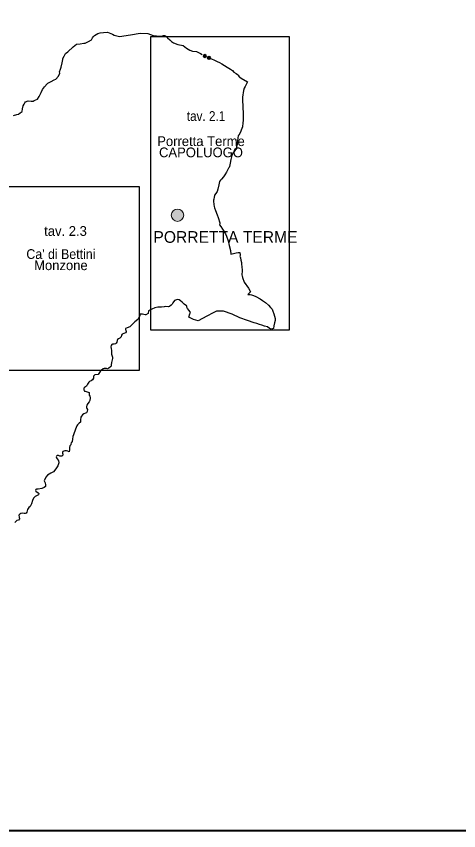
# Model space of a CAD drawing. Extents: x 650468 to 655025, y 889970 to 891591.
# Drawn here: x 653140 to 653594, y 889970 to 890806 of the extents above; entities that cross this region are included whole.
import ezdxf
from ezdxf.enums import TextEntityAlignment as Align

# ---------------------------------------------------------------- set-up
doc = ezdxf.new("R2010")
doc.units = 0
doc.header["$LTSCALE"] = 5.6
doc.header["$PDMODE"] = 32
doc.header["$PDSIZE"] = 2.8
doc.layers.add('61', color=7, linetype='Continuous', lineweight=35)

msp = doc.modelspace()

# ---------------------------------------------------------------- hatches: boundary and pattern name
at = {"layer": '61'}
msp.add_hatch(color=256, dxfattribs=at).paths.add_polyline_path([(653311.55, 890601.85, 1), (653298.83, 890601.85, 1)])

# ---------------------------------------------------------------- linework, layer by layer
at = {"layer": '61', "lineweight": 40}
msp.add_lwpolyline([(653618.27, 891591.08), (653618.27, 889969.62), (652568.28, 889969.62), (652568.28, 891591.08)], close=True, dxfattribs=at)
at = {"layer": '61', "lineweight": 25}
for points in [[(653183.06, 890744.54), (653184.28, 890747.62), (653184.04, 890749.25), (653185.06, 890751.73), (653185.58, 890753.74), (653186.72, 890758.18), (653187.32, 890761.66), (653187.32, 890762.7), (653188.7, 890765.25), (653190.18, 890768.02), (653192.6, 890769.58), (653197.9, 890774.61), (653199.68, 890776.21), (653201.54, 890777.37), (653205.34, 890777.82), (653209.1, 890778.42), (653210.28, 890778.65), (653213.66, 890780.37), (653216.98, 890781.81), (653217.8, 890783.98), (653218.58, 890785.09), (653220.08, 890786.37), (653221.56, 890787.53), (653223.4, 890788.42), (653225.9, 890789.3), (653229.24, 890789.65), (653233.22, 890789.94), (653236.66, 890788.5), (653238.56, 890787.65), (653240.32, 890786.93), (653245.46, 890785.53), (653256.86, 890787.22), (653266.82, 890788.86), (653274.84, 890788.41), (653280.14, 890786.46), (653283.48, 890786.21), (653288.3, 890785.85), (653290.94, 890786.41), (653291.9, 890786.34), (653292.8, 890785.94)], [(653292.8, 890785.94), (653293.7, 890785.33), (653295.02, 890784.09), (653297.26, 890781.98), (653298.98, 890780.29), (653301.26, 890778.81), (653305.46, 890777.1), (653310.86, 890775.98), (653314.46, 890773.57), (653318, 890771.41), (653320.46, 890770.26), (653324.72, 890769.97), (653328.8, 890768.06), (653330.44, 890766.89)], [(653337.54, 890763.38), (653342.48, 890761.58), (653346.08, 890759.69), (653348.18, 890758.66), (653350.58, 890757.22), (653353.4, 890755.61), (653356.1, 890753.74), (653359.64, 890751.9), (653361.56, 890750.46), (653363.1, 890748.77), (653365.58, 890747.26), (653366.96, 890746.5), (653367.5, 890745.66), (653368.66, 890743.98), (653369.18, 890743.46), (653370.76, 890742.45), (653377.22, 890738.7), (653374.64, 890734.02), (653373.8, 890732.17), (653373.1, 890730.06), (653371.82, 890723.1), (653371.88, 890718.1), (653372.2, 890715.66), (653372.36, 890710.54), (653372.52, 890708.66), (653372.74, 890706.25), (653372.72, 890699.14), (653372.3, 890696.73), (653372.14, 890695.49), (653372.08, 890694.09), (653371.88, 890692.33), (653371.72, 890691.81), (653370.14, 890688.3), (653368.06, 890683.62), (653367.64, 890683.54), (653366.9, 890678.26), (653366.6, 890676.69), (653366.4, 890674.41), (653365.96, 890672.17), (653365.64, 890670.18)], [(653136.74, 890704.13), (653140.26, 890705.14), (653142.04, 890705.62), (653143.64, 890707.02), (653145.62, 890708.5), (653145.98, 890711.26), (653146.64, 890714.22), (653147.58, 890716.06), (653148.38, 890717.13), (653149.04, 890718.34), (653151.94, 890719.38), (653154.8, 890719.14), (653156.88, 890719.09), (653158.02, 890719.66), (653161.46, 890720.98), (653162.96, 890723.77), (653165.1, 890727.81), (653166.7, 890730.97), (653168.72, 890733.81), (653171.22, 890736.86), (653172, 890737.42), (653175.44, 890739.06), (653178.6, 890740.74), (653180.26, 890741.49), (653183.06, 890744.54)], [(653365.64, 890670.18), (653365.44, 890669.49), (653364.5, 890668.5), (653363.5, 890667.42), (653362.86, 890666.54), (653362.12, 890665.49), (653361.12, 890663.18), (653360.58, 890661.82), (653359.88, 890658.89), (653359.2, 890655.45), (653358.46, 890651.77), (653358.2, 890650.97), (653357.66, 890650.06), (653355.4, 890646.05), (653353.82, 890643.33), (653352.46, 890641.34), (653350.36, 890638.81), (653349.46, 890637.69), (653348.44, 890636.46), (653347.68, 890633.05), (653346.66, 890628.7), (653346.02, 890626.09), (653344.5, 890624.25), (653343.08, 890622.33), (653343.08, 890621.94), (653343.02, 890620.26), (653342.46, 890618.17), (653342.2, 890617.18), (653342.32, 890616.25), (653342.58, 890612.85), (653342.84, 890610.93), (653343.34, 890609.5), (653344.3, 890606.78), (653345.9, 890602.38), (653347.04, 890599.61), (653348.58, 890594.09), (653348.58, 890593.33), (653348.32, 890592.09), (653349.74, 890590.3), (653351.52, 890587.57)], [(653351.52, 890587.57), (653354.44, 890582.86), (653355.46, 890580.21), (653357.32, 890575.5), (653358.34, 890570.81), (653359.48, 890565.53), (653360.06, 890561.86), (653361.2, 890562.22), (653365.34, 890563.22), (653367.4, 890563.61), (653369.18, 890563.49), (653369.62, 890561.3), (653369.44, 890560.38), (653369.3, 890559.82), (653369.76, 890558.14), (653370.32, 890555.62), (653370.78, 890553.38), (653371.04, 890551.41), (653371.28, 890548.93), (653371.54, 890545.53), (653371.74, 890544.54), (653371.42, 890540.62), (653371.6, 890539.3), (653372.06, 890538.57), (653372, 890538.01), (653373.58, 890533.06), (653378, 890526.74), (653380.22, 890523.05), (653377.58, 890520.3), (653379, 890520.25), (653380, 890520.34), (653381.36, 890520.02), (653383.4, 890519.33), (653385.66, 890518.3), (653390, 890515.89), (653392.6, 890514.26), (653395.74, 890512.1), (653398.66, 890509.5), (653400.64, 890507.18), (653402.3, 890505.26)], [(653302, 890514.22), (653300.3, 890511.9), (653299.76, 890510.58), (653298.62, 890509.54), (653296.84, 890507.94), (653295.82, 890507.89), (653292.58, 890507.97), (653291.42, 890507.89), (653288.64, 890507.5), (653285.04, 890507.22), (653281.76, 890506.57), (653278.78, 890505.38), (653275.38, 890503.62), (653274.98, 890500.98), (653272.8, 890499.38), (653271.86, 890499.58), (653269.34, 890500.13), (653266.94, 890500.18), (653266.08, 890497.81), (653264.44, 890494.7), (653261.52, 890492.26), (653258.8, 890489.58), (653256.28, 890487.26), (653253.62, 890486.14), (653251.96, 890485.57), (653251.7, 890484.53), (653252.18, 890483.73), (653252.5, 890482.14), (653251.9, 890481.09), (653250, 890480.3), (653248.22, 890479.5), (653247.74, 890478.58), (653247.34, 890476.81), (653246.1, 890475.7), (653244.58, 890474.81), (653243.72, 890474.14), (653243.18, 890473.25), (653242.88, 890471.38), (653242.2, 890470.3), (653241.46, 890469.65)], [(653402.3, 890505.26), (653403.2, 890503.29), (653404.22, 890500.62), (653405.48, 890495.78), (653405.36, 890493.73), (653404.74, 890491.37), (653404.06, 890488.3), (653403.78, 890485.49), (653401.76, 890484.9), (653399.84, 890485.54), (653397.54, 890487.01), (653394.48, 890487.78), (653391.76, 890488.86), (653389.58, 890489.5), (653386.8, 890490.62), (653384, 890491.37), (653377.22, 890493.54), (653369.32, 890496.57), (653361.44, 890500.02), (653352.32, 890503.26), (653345.24, 890503.38), (653341.72, 890501.41), (653335.46, 890498.13), (653326.36, 890493.42), (653321.48, 890494.77), (653316.92, 890497.02), (653318.02, 890500.42), (653318.7, 890501.89), (653317.28, 890503.98), (653315.64, 890505.97), (653314.82, 890507.42), (653314.82, 890508.74), (653314.48, 890508.89), (653311.9, 890510.46), (653309.94, 890512.57), (653308.3, 890513.89), (653306.94, 890514.94), (653305.58, 890515.14), (653304.12, 890514.89), (653302, 890514.22)], [(653241.46, 890469.65), (653240.06, 890469.26), (653238.54, 890469.22), (653237.86, 890469.02), (653237.12, 890467.94), (653236.74, 890466.7), (653237.02, 890464.9), (653237.48, 890462.93), (653237.54, 890461.34), (653237.54, 890459.26), (653237.68, 890458.02), (653238.02, 890456.98), (653238.32, 890456.01), (653238.32, 890454.73), (653238.16, 890453.3), (653237.58, 890450.46), (653236.94, 890448.3), (653237, 890446.86), (653236.32, 890445.93), (653234.74, 890444.78), (653233.28, 890444.09), (653232.16, 890444.22), (653229.82, 890444.22), (653229, 890443.89), (653226.94, 890442.29), (653225.72, 890441.18), (653223.68, 890438.26), (653220.46, 890437.89), (653218.94, 890436.61), (653218.9, 890434.29), (653217.98, 890432.69), (653216.36, 890431.82), (653214.86, 890430.97), (653213.98, 890430.21), (653212.92, 890428.41), (653211.64, 890426.14), (653210.82, 890425.66), (653209.74, 890424.94), (653209.16, 890424.21), (653208.92, 890423.34)], [(653208.92, 890423.34), (653208.96, 890422.45), (653209.7, 890421.22), (653210.52, 890420.94), (653212.58, 890420.37), (653214.32, 890419.57), (653214.52, 890418.01), (653214.56, 890417.05), (653215.1, 890415.89), (653215.4, 890414.74), (653215.4, 890413.85), (653215.06, 890411.62), (653214.42, 890410.25), (653213.2, 890408.45), (653212.08, 890406.66), (653211.68, 890405.46), (653211.74, 890404.29), (653212.14, 890403.22), (653212.74, 890402.21), (653212.54, 890400.1), (653211.66, 890398.89), (653210.84, 890398.41), (653209.04, 890397.78), (653207.66, 890396.7), (653206.54, 890395.53), (653205.86, 890394.3), (653205.42, 890391.73), (653205.52, 890389.18), (653204.1, 890388.18), (653202.64, 890386.58), (653201.86, 890385.65), (653200.44, 890381.98), (653198.48, 890376.26), (653197.76, 890374.41), (653197.38, 890371.73), (653196.88, 890369.3), (653196.02, 890368.02), (653195.76, 890366.74), (653195.48, 890365.94), (653194.46, 890364.9)], [(653194.46, 890364.9), (653194.2, 890363.38), (653194.3, 890362.06), (653194.3, 890360.7), (653193.8, 890358.74), (653192.68, 890359.3), (653191.04, 890359.7), (653189.32, 890359.74), (653188.34, 890359.61), (653187.56, 890358.98), (653187.08, 890358.18), (653187.02, 890357.38), (653187.28, 890356.29), (653187.28, 890355.3), (653186.54, 890354.45), (653185.18, 890354.26), (653184.44, 890354.5), (653182.94, 890355.01), (653181.72, 890354.97), (653181.02, 890354.5), (653180.64, 890353.54), (653180.84, 890352.66), (653181.48, 890351.61), (653182.54, 890350.38), (653182.84, 890349.73), (653183.24, 890347.65), (653182.46, 890344.34), (653180.3, 890341.22), (653177.86, 890338.09), (653175.14, 890336.77), (653173.46, 890335.82), (653171.62, 890334.89), (653169.96, 890332.61), (653168.4, 890329.1), (653169.18, 890326.85), (653169.48, 890324.74), (653169.48, 890323.33), (653168.3, 890322.3), (653165.78, 890321.06), (653162.06, 890320.5)], [(653162.06, 890320.5), (653160.5, 890320.41), (653159.62, 890320.02), (653159.42, 890319.06), (653159.82, 890318.22), (653162.06, 890316.7), (653162.74, 890315.94), (653162.46, 890314.73), (653161.1, 890313.86), (653158.84, 890312.74), (653157.38, 890311.13), (653156.42, 890308.9), (653155.36, 890305.22), (653153.9, 890302.49), (653152.34, 890301.54), (653151.08, 890299.65), (653150.48, 890296.98), (653149.7, 890295.66), (653148.74, 890295.29), (653147.56, 890295.46), (653145.62, 890295.77), (653144.44, 890295.57), (653143.28, 890294.9), (653142.3, 890293.58), (653142.68, 890291.7), (653142.78, 890289.81), (653141.9, 890288.74), (653140.24, 890288.18), (653139.74, 890287.9), (653138.1, 890286.21)]]:
    msp.add_lwpolyline(points, dxfattribs=at)
for points in [[(653277.73, 890785.4), (653419.81, 890785.4), (653419.81, 890483.87), (653277.73, 890483.87)], [(653114.54, 890631.33), (653265.86, 890631.33), (653265.86, 890442.31), (653114.54, 890442.31)]]:
    msp.add_lwpolyline(points, close=True, dxfattribs=at)
at = {"layer": '61', "lineweight": 13}
msp.add_circle((653305.19, 890601.85), 6.36, dxfattribs=at)
at = {"layer": '61'}
for p in [(653333.36, 890765.38), (653337.54, 890763.38)]:
    msp.add_point(p, dxfattribs=at)

# ---------------------------------------------------------------- texts
at = {"layer": '61', "width": 0.9}
msp.add_text('tav. 2.1', height=10, dxfattribs=at).set_placement((653314.75, 890698.69))
at = {"layer": '61'}
for s, height, p in [('Porretta Terme', 10, (653329.33, 890672.87)), ('CAPOLUOGO', 10, (653329.32, 890661.37)), ('PORRETTA TERME', 12, (653354.46, 890573.47)), ('Monzone', 10, (653185.44, 890545.42))]:
    msp.add_text(s, height=height, dxfattribs=at).set_placement(p, align=Align.CENTER)
msp.add_text('tav. 2.3', height=10, dxfattribs=at).set_placement((653168.26, 890580.61))
at = {"layer": '61', "width": 0.95}
msp.add_text("Ca' di Bettini", height=10, dxfattribs=at).set_placement((653185.44, 890556.92), align=Align.CENTER)

doc.saveas('drawing.dxf')
